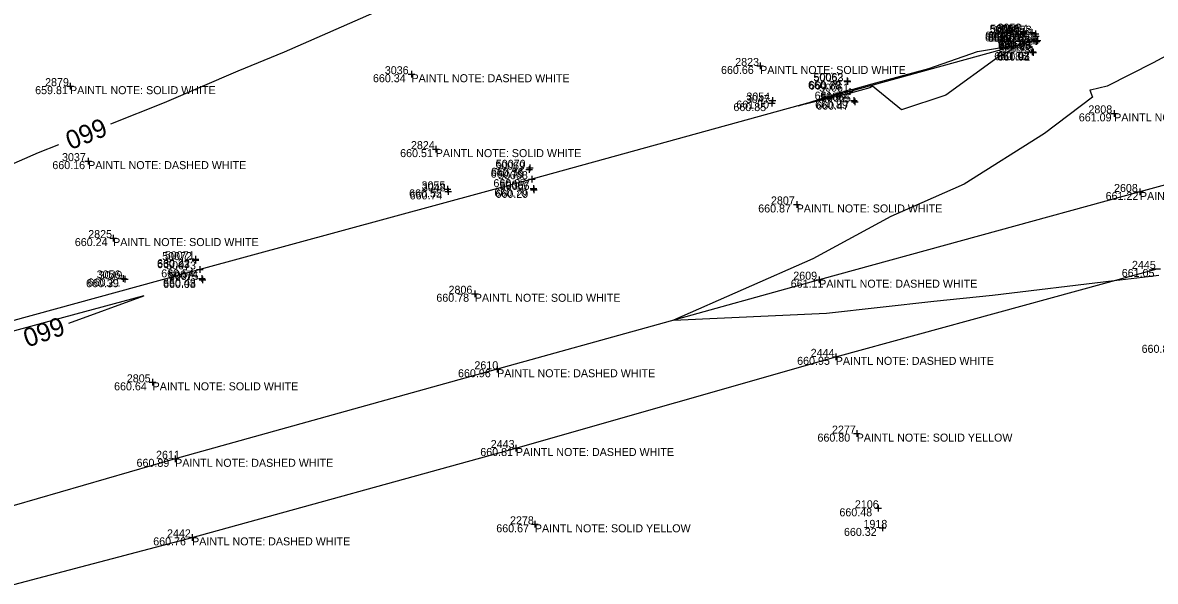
# Model space of a CAD drawing. Extents: x 2129350 to 2137777, y 657588 to 659885.
# Drawn here: x 2133578.5 to 2133748.4, y 658855.6 to 658939.3 of the extents above; entities that cross this region are included whole.
import ezdxf

# ---------------------------------------------------------------- set-up
doc = ezdxf.new("R2010")
doc.units = 0
for name, color, linetype in [('DT_X_Contour_Major', 7, 'Continuous'), ('DT_X_Contour_Minor', 7, 'Continuous'), ('PV_X_COP', 7, 'Continuous'), ('SV_X_Shot_Marker', 7, 'Continuous'), ('SV_X_Text_Comment', 7, 'Continuous'), ('SV_X_Text_Elevation', 7, 'Continuous'), ('SV_X_Text_Name', 7, 'Continuous')]:
    doc.layers.add(name, color=color, linetype=linetype)

msp = doc.modelspace()

# ---------------------------------------------------------------- linework, layer by layer
at = {"layer": 'DT_X_Contour_Major'}
for points in [[(2133591.75, 658924.14), (2133599.79, 658927.35), (2133610.86, 658932.13), (2133617.82, 658934.95), (2133634.09, 658942.09), (2133634.1, 658942.1), (2133634.22, 658942.15), (2133635.49, 658942.71), (2133639.66, 658944.47), (2133655.46, 658950.08), (2133660.34, 658951.83), (2133675.97, 658957.4), (2133684.82, 658960.59)], [(2133519.86, 658880.59), (2133520.81, 658880.85), (2133528.99, 658883.14), (2133535.75, 658885.05), (2133553.84, 658890.1), (2133553.85, 658890.1), (2133555.64, 658890.59), (2133556.82, 658890.91), (2133560.13, 658891.82), (2133558.94, 658891.52), (2133555.9, 658890.81), (2133550.49, 658894.1), (2133548.57, 658895.21), (2133555.23, 658903.95), (2133560.36, 658910.88), (2133564.1, 658912.51), (2133580.92, 658919.85), (2133583.95, 658921.04)], [(2133585.46, 658894.27), (2133596.7, 658898.35), (2133584.65, 658895.1), (2133581.35, 658894.2), (2133564.73, 658889.7), (2133557.21, 658887.65), (2133555.93, 658887.3), (2133555.26, 658887.12), (2133541.84, 658883.44), (2133531.15, 658880.51), (2133512.8, 658875.49), (2133511.75, 658875.21)]]:
    msp.add_lwpolyline(points, dxfattribs=at)
at = {"layer": 'DT_X_Contour_Minor'}
for points in [[(2133763.9, 658941.81), (2133748.12, 658933.31), (2133741.2, 658929.8), (2133738.68, 658929.2), (2133738.58, 658929.22), (2133738.99, 658928.18), (2133731.79, 658922.73), (2133719.77, 658915.11), (2133708.76, 658910.26), (2133697.07, 658903.92), (2133697.04, 658903.91), (2133676.14, 658894.71), (2133699.09, 658895.75), (2133715.18, 658897.58), (2133724.01, 658898.45), (2133742.27, 658900.65), (2133747.36, 658901.25), (2133748.96, 658901.49)], [(2133730.41, 658936.56), (2133730.2, 658936.88), (2133730.18, 658936.62), (2133730.41, 658936.56)], [(2133705.98, 658929.83), (2133705.62, 658929.56), (2133702.72, 658928.75), (2133699.84, 658928.05), (2133694.91, 658926.87), (2133700.9, 658928.74), (2133702.67, 658929.3), (2133703.09, 658929.35), (2133705.97, 658930.14), (2133714.45, 658932.47), (2133721.75, 658935.01), (2133728.35, 658936.11), (2133724.84, 658934.14), (2133716.98, 658928.46), (2133710.33, 658926.27), (2133705.98, 658929.83)]]:
    msp.add_lwpolyline(points, dxfattribs=at)
at = {"layer": 'PV_X_COP'}
for points in [[(2133730.22, 658936.63), (2133702.62, 658928.99), (2133654.91, 658915.86), (2133605.08, 658902.34), (2133554.92, 658888.56), (2133509.82, 658876.27), (2133459.08, 658862.07), (2133410.5, 658848.76), (2133362.33, 658835.49), (2133317.19, 658823.07), (2133266.35, 658808.95), (2133217.78, 658795.57), (2133170.89, 658782.95), (2133115.31, 658767.84), (2133063.51, 658753.59), (2133014.74, 658740.25), (2132963.88, 658726.32), (2132916.79, 658713.58), (2132868.39, 658700.1), (2132821.62, 658687.28), (2132770.55, 658673.15), (2132722.89, 658660.22), (2132675.02, 658647)], [(2133794.81, 658927.21), (2133746.12, 658913.94), (2133698.01, 658900.79), (2133649.69, 658887.36), (2133601.4, 658873.93), (2133553.07, 658859.93), (2133504.83, 658847.66), (2133456.81, 658834.24), (2133407.74, 658820.79), (2133360.25, 658807.48), (2133312.09, 658793.76), (2133264.31, 658781.06), (2133215.32, 658767.73), (2133166.74, 658754.23)], [(2133170.2, 658742.4), (2133218.35, 658756.09), (2133267.35, 658769.51), (2133315.65, 658782.23), (2133362.85, 658795.38), (2133411.68, 658809.49), (2133460, 658822.86), (2133507.59, 658836.18), (2133555.89, 658849.51), (2133603.94, 658862.15), (2133652.51, 658875.55), (2133700.49, 658889.22), (2133748.69, 658902.41)]]:
    msp.add_lwpolyline(points, dxfattribs=at)
at = {"layer": 'SV_X_Shot_Marker'}
for p, q in [((2133728.18, 658938.13), (2133728.18, 658937.13)), ((2133728.66, 658938.23), (2133728.66, 658937.23)), ((2133728.67, 658938.49), (2133728.67, 658937.49)), ((2133728.7, 658938.35), (2133728.7, 658937.35)), ((2133729.92, 658938.34), (2133729.92, 658937.34)), ((2133730.44, 658938.17), (2133730.44, 658937.17)), ((2133727.68, 658937.63), (2133728.68, 658937.63)), ((2133728.16, 658937.73), (2133729.16, 658937.73)), ((2133728.17, 658937.99), (2133729.17, 658937.99)), ((2133728.18, 658937.63), (2133728.18, 658937.63)), ((2133728.2, 658937.85), (2133729.2, 658937.85)), ((2133728.66, 658937.73), (2133728.66, 658937.73)), ((2133728.67, 658937.99), (2133728.67, 658937.99)), ((2133728.7, 658937.85), (2133728.7, 658937.85)), ((2133729.42, 658937.84), (2133730.42, 658937.84)), ((2133729.7, 658936.91), (2133730.7, 658936.91)), ((2133729.72, 658936.63), (2133730.72, 658936.63)), ((2133729.92, 658937.84), (2133729.92, 658937.84)), ((2133729.94, 658937.67), (2133730.94, 658937.67)), ((2133729.98, 658937.32), (2133730.98, 658937.32)), ((2133730, 658936.52), (2133731, 658936.52)), ((2133730.11, 658936.5), (2133731.11, 658936.5)), ((2133730.2, 658937.41), (2133730.2, 658936.41)), ((2133730.2, 658936.91), (2133730.2, 658936.91)), ((2133730.22, 658937.13), (2133730.22, 658936.13)), ((2133730.22, 658936.63), (2133730.22, 658936.63)), ((2133730.24, 658936.66), (2133731.24, 658936.66)), ((2133730.44, 658937.67), (2133730.44, 658937.67)), ((2133730.48, 658937.82), (2133730.48, 658936.82)), ((2133730.48, 658937.32), (2133730.48, 658937.32)), ((2133730.5, 658937.02), (2133730.5, 658936.02)), ((2133730.5, 658936.52), (2133730.5, 658936.52)), ((2133730.61, 658937), (2133730.61, 658936)), ((2133730.61, 658936.5), (2133730.61, 658936.5)), ((2133730.74, 658937.16), (2133730.74, 658936.16)), ((2133730.74, 658936.66), (2133730.74, 658936.66)), ((2133729.43, 658934.96), (2133730.43, 658934.96)), ((2133729.48, 658934.96), (2133730.48, 658934.96)), ((2133729.6, 658934.84), (2133730.6, 658934.84)), ((2133729.61, 658934.9), (2133730.61, 658934.9)), ((2133729.93, 658935.46), (2133729.93, 658934.46)), ((2133729.93, 658934.96), (2133729.93, 658934.96)), ((2133729.98, 658935.46), (2133729.98, 658934.46)), ((2133729.98, 658934.96), (2133729.98, 658934.96)), ((2133730.1, 658935.34), (2133730.1, 658934.34)), ((2133730.1, 658934.84), (2133730.1, 658934.84)), ((2133730.11, 658935.4), (2133730.11, 658934.4)), ((2133730.11, 658934.9), (2133730.11, 658934.9)), ((2133689.15, 658933.34), (2133689.15, 658932.34)), ((2133636.35, 658931.6), (2133637.35, 658931.6)), ((2133636.85, 658932.1), (2133636.85, 658931.1)), ((2133636.85, 658931.6), (2133636.85, 658931.6)), ((2133688.65, 658932.84), (2133689.65, 658932.84)), ((2133689.15, 658932.84), (2133689.15, 658932.84)), ((2133585.13, 658929.81), (2133586.13, 658929.81)), ((2133585.63, 658930.31), (2133585.63, 658929.31)), ((2133585.63, 658929.81), (2133585.63, 658929.81)), ((2133701.68, 658930.59), (2133702.68, 658930.59)), ((2133701.73, 658930.5), (2133702.73, 658930.5)), ((2133702.18, 658931.09), (2133702.18, 658930.09)), ((2133702.18, 658930.59), (2133702.18, 658930.59)), ((2133702.23, 658931), (2133702.23, 658930)), ((2133702.23, 658930.5), (2133702.23, 658930.5)), ((2133690.98, 658928.15), (2133690.98, 658927.15)), ((2133702.12, 658928.99), (2133703.12, 658928.99)), ((2133702.62, 658929.49), (2133702.62, 658928.49)), ((2133702.62, 658928.99), (2133702.62, 658928.99)), ((2133703.18, 658928.14), (2133703.18, 658927.14)), ((2133703.34, 658927.98), (2133703.34, 658926.98)), ((2133690.41, 658927.27), (2133691.41, 658927.27)), ((2133690.48, 658927.65), (2133691.48, 658927.65)), ((2133690.91, 658927.77), (2133690.91, 658926.77)), ((2133690.91, 658927.27), (2133690.91, 658927.27)), ((2133690.98, 658927.65), (2133690.98, 658927.65)), ((2133702.68, 658927.64), (2133703.68, 658927.64)), ((2133702.84, 658927.48), (2133703.84, 658927.48)), ((2133703.18, 658927.64), (2133703.18, 658927.64)), ((2133703.34, 658927.48), (2133703.34, 658927.48)), ((2133742.26, 658926.23), (2133742.26, 658925.23)), ((2133741.76, 658925.73), (2133742.76, 658925.73)), ((2133742.26, 658925.73), (2133742.26, 658925.73)), ((2133639.99, 658920.37), (2133640.99, 658920.37)), ((2133640.49, 658920.87), (2133640.49, 658919.87)), ((2133640.49, 658920.37), (2133640.49, 658920.37)), ((2133587.85, 658918.57), (2133588.85, 658918.57)), ((2133588.35, 658919.07), (2133588.35, 658918.07)), ((2133588.35, 658918.57), (2133588.35, 658918.57)), ((2133654.48, 658917.79), (2133654.48, 658916.79)), ((2133654.62, 658918.07), (2133654.62, 658917.07)), ((2133653.98, 658917.29), (2133654.98, 658917.29)), ((2133654.12, 658917.57), (2133655.12, 658917.57)), ((2133654.48, 658917.29), (2133654.48, 658917.29)), ((2133654.62, 658917.57), (2133654.62, 658917.57)), ((2133654.91, 658916.36), (2133654.91, 658915.36)), ((2133641.76, 658914.34), (2133642.76, 658914.34)), ((2133642.26, 658914.84), (2133642.26, 658913.84)), ((2133642.26, 658914.34), (2133642.26, 658914.34)), ((2133642.33, 658914.53), (2133642.33, 658913.53)), ((2133654.41, 658915.86), (2133655.41, 658915.86)), ((2133654.63, 658914.45), (2133655.63, 658914.45)), ((2133654.72, 658914.26), (2133655.72, 658914.26)), ((2133654.91, 658915.86), (2133654.91, 658915.86)), ((2133655.13, 658914.95), (2133655.13, 658913.95)), ((2133655.13, 658914.45), (2133655.13, 658914.45)), ((2133655.22, 658914.76), (2133655.22, 658913.76)), ((2133655.22, 658914.26), (2133655.22, 658914.26)), ((2133746.12, 658914.44), (2133746.12, 658913.44)), ((2133641.83, 658914.03), (2133642.83, 658914.03)), ((2133642.33, 658914.03), (2133642.33, 658914.03)), ((2133694.63, 658912.57), (2133694.63, 658911.57)), ((2133745.62, 658913.94), (2133746.62, 658913.94)), ((2133746.12, 658913.94), (2133746.12, 658913.94)), ((2133694.13, 658912.07), (2133695.13, 658912.07)), ((2133694.63, 658912.07), (2133694.63, 658912.07)), ((2133592.09, 658907.53), (2133592.09, 658906.53)), ((2133591.59, 658907.03), (2133592.59, 658907.03)), ((2133592.09, 658907.03), (2133592.09, 658907.03)), ((2133604.43, 658904.35), (2133604.43, 658903.35)), ((2133604.46, 658904.22), (2133604.46, 658903.22)), ((2133603.93, 658903.85), (2133604.93, 658903.85)), ((2133603.96, 658903.72), (2133604.96, 658903.72)), ((2133604.43, 658903.85), (2133604.43, 658903.85)), ((2133604.46, 658903.72), (2133604.46, 658903.72)), ((2133605.08, 658902.84), (2133605.08, 658901.84)), ((2133748.19, 658902.41), (2133749.19, 658902.41)), ((2133593.11, 658900.98), (2133594.11, 658900.98)), ((2133593.34, 658900.86), (2133594.34, 658900.86)), ((2133593.61, 658901.48), (2133593.61, 658900.48)), ((2133593.61, 658900.98), (2133593.61, 658900.98)), ((2133593.84, 658901.36), (2133593.84, 658900.36)), ((2133593.84, 658900.86), (2133593.84, 658900.86)), ((2133604.58, 658902.34), (2133605.58, 658902.34)), ((2133604.88, 658900.96), (2133605.88, 658900.96)), ((2133604.98, 658900.75), (2133605.98, 658900.75)), ((2133605.08, 658902.34), (2133605.08, 658902.34)), ((2133605.38, 658901.46), (2133605.38, 658900.46)), ((2133605.38, 658900.96), (2133605.38, 658900.96)), ((2133605.48, 658901.25), (2133605.48, 658900.25)), ((2133605.48, 658900.75), (2133605.48, 658900.75)), ((2133697.51, 658900.79), (2133698.51, 658900.79)), ((2133698.01, 658901.29), (2133698.01, 658900.29)), ((2133698.01, 658900.79), (2133698.01, 658900.79)), ((2133646.35, 658899.18), (2133646.35, 658898.18)), ((2133645.85, 658898.68), (2133646.85, 658898.68)), ((2133646.35, 658898.68), (2133646.35, 658898.68)), ((2133699.99, 658889.22), (2133700.99, 658889.22)), ((2133700.49, 658889.72), (2133700.49, 658888.72)), ((2133700.49, 658889.22), (2133700.49, 658889.22)), ((2133649.19, 658887.36), (2133650.19, 658887.36)), ((2133649.69, 658887.86), (2133649.69, 658886.86)), ((2133649.69, 658887.36), (2133649.69, 658887.36)), ((2133597.52, 658885.4), (2133598.52, 658885.4)), ((2133598.02, 658885.9), (2133598.02, 658884.9)), ((2133598.02, 658885.4), (2133598.02, 658885.4)), ((2133703.13, 658877.71), (2133704.13, 658877.71)), ((2133703.63, 658878.21), (2133703.63, 658877.21)), ((2133703.63, 658877.71), (2133703.63, 658877.71)), ((2133652.01, 658875.55), (2133653.01, 658875.55)), ((2133652.51, 658876.05), (2133652.51, 658875.05)), ((2133652.51, 658875.55), (2133652.51, 658875.55)), ((2133600.9, 658873.93), (2133601.9, 658873.93)), ((2133601.4, 658874.43), (2133601.4, 658873.43)), ((2133601.4, 658873.93), (2133601.4, 658873.93)), ((2133706.83, 658867.01), (2133706.83, 658866.01)), ((2133706.33, 658866.51), (2133707.33, 658866.51)), ((2133706.83, 658866.51), (2133706.83, 658866.51)), ((2133654.86, 658864.11), (2133655.86, 658864.11)), ((2133655.36, 658864.61), (2133655.36, 658863.61)), ((2133655.36, 658864.11), (2133655.36, 658864.11)), ((2133707.01, 658863.57), (2133708.01, 658863.57)), ((2133707.51, 658864.07), (2133707.51, 658863.07)), ((2133707.51, 658863.57), (2133707.51, 658863.57)), ((2133603.44, 658862.15), (2133604.44, 658862.15)), ((2133603.94, 658862.65), (2133603.94, 658861.65)), ((2133603.94, 658862.15), (2133603.94, 658862.15))]:
    msp.add_line(p, q, dxfattribs=at)

# ---------------------------------------------------------------- texts
at = {"layer": 'DT_X_Contour_Major'}
for rotation, p in [(201.661, (2133590.45, 658925.12)), (199.343, (2133584.2, 658895.31))]:
    msp.add_text('660', height=2.8, rotation=rotation, dxfattribs=at).set_placement(p)
at = {"layer": 'SV_X_Text_Comment'}
for s, p in [('PAINTL NOTE: DASHED WHITE', (2133636.85, 658930.4)), ('PAINTL NOTE: SOLID WHITE', (2133689.15, 658931.64)), ('PAINTL NOTE: SOLID WHITE', (2133585.63, 658928.61)), ('PAINTL NOTE: SOLID WHITE', (2133742.26, 658924.53)), ('PAINTL NOTE: SOLID WHITE', (2133640.49, 658919.17)), ('PAINTL NOTE: DASHED WHITE', (2133588.35, 658917.37)), ('PAINTL NOTE: DASHED WHITE', (2133746.12, 658912.74)), ('PAINTL NOTE: SOLID WHITE', (2133694.63, 658910.87)), ('PAINTL NOTE: SOLID WHITE', (2133592.09, 658905.83)), ('PAINTL NOTE: DASHED WHITE', (2133698.01, 658899.59)), ('PAINTL NOTE: SOLID WHITE', (2133646.35, 658897.48)), ('PAINTL NOTE: DASHED WHITE', (2133700.49, 658888.02)), ('PAINTL NOTE: DASHED WHITE', (2133649.69, 658886.16)), ('PAINTL NOTE: SOLID WHITE', (2133598.02, 658884.2)), ('PAINTL NOTE: SOLID YELLOW', (2133703.63, 658876.51)), ('PAINTL NOTE: DASHED WHITE', (2133652.51, 658874.35)), ('PAINTL NOTE: DASHED WHITE', (2133601.4, 658872.73)), ('PAINTL NOTE: SOLID YELLOW', (2133655.36, 658862.91)), ('PAINTL NOTE: DASHED WHITE', (2133603.94, 658860.95))]:
    msp.add_text(s, height=1.2, dxfattribs=at).set_placement(p)
at = {"layer": 'SV_X_Text_Elevation'}
for s, p in [('660.97', (2133722.87, 658936.53)), ('660.87', (2133722.9, 658936.79)), ('661.01', (2133723.31, 658936.43)), ('660.81', (2133723.36, 658936.65)), ('660.87', (2133724.15, 658936.65)), ('660.89', (2133724.66, 658936.47)), ('660.97', (2133724.69, 658936.12)), ('660.88', (2133724.83, 658935.3)), ('661.06', (2133724.85, 658935.43)), ('661.04', (2133724.91, 658935.71)), ('660.93', (2133724.95, 658935.46)), ('661.03', (2133725.2, 658935.32)), ('660.86', (2133724.26, 658933.7)), ('661.02', (2133724.64, 658933.76)), ('661.03', (2133724.68, 658933.76)), ('660.91', (2133724.74, 658933.64)), ('660.34', (2133631.07, 658930.4)), ('660.66', (2133683.28, 658931.64)), ('659.81', (2133580.4, 658928.61)), ('660.70', (2133696.33, 658929.4)), ('660.88', (2133696.45, 658929.3)), ('661.07', (2133697.32, 658927.79)), ('660.85', (2133685.14, 658926.07)), ('661.00', (2133685.57, 658926.45)), ('660.89', (2133697.4, 658926.44)), ('660.47', (2133697.56, 658926.29)), ('661.09', (2133736.95, 658924.53)), ('660.51', (2133635.15, 658919.17)), ('660.16', (2133582.98, 658917.37)), ('660.75', (2133648.72, 658916.09)), ('660.56', (2133648.77, 658916.37)), ('660.55', (2133636.49, 658913.14)), ('660.87', (2133649.14, 658914.66)), ('660.70', (2133649.28, 658913.25)), ('660.29', (2133649.45, 658913.06)), ('660.74', (2133636.58, 658912.83)), ('661.22', (2133740.97, 658912.74)), ('660.87', (2133688.86, 658910.87)), ('660.24', (2133586.35, 658905.83)), ('660.43', (2133598.68, 658902.52)), ('660.22', (2133598.69, 658902.66)), ('660.54', (2133599.31, 658901.14)), ('661.05', (2133743.39, 658901.2)), ('660.39', (2133588.04, 658899.66)), ('660.21', (2133588.29, 658899.78)), ('660.08', (2133599.59, 658899.55)), ('660.43', (2133599.59, 658899.76)), ('661.11', (2133693.73, 658899.59)), ('660.78', (2133640.58, 658897.48)), ('660.89', (2133746.37, 658889.82)), ('660.95', (2133694.7, 658888.02)), ('660.96', (2133643.83, 658886.16)), ('660.64', (2133592.24, 658884.2)), ('660.80', (2133697.75, 658876.51)), ('660.81', (2133647.17, 658874.35)), ('660.89', (2133595.61, 658872.73)), ('660.48', (2133701.04, 658865.31)), ('660.67', (2133649.57, 658862.91)), ('660.32', (2133701.72, 658862.37)), ('660.76', (2133598.11, 658860.95))]:
    msp.add_text(s, height=1.2, dxfattribs=at).set_placement(p)
at = {"layer": 'SV_X_Text_Name'}
for s, p in [('50056', (2133723.55, 658937.73)), ('50055', (2133723.66, 658937.85)), ('3046', (2133724.19, 658937.63)), ('3053', (2133724.77, 658937.99)), ('50054', (2133724.89, 658937.84)), ('50053', (2133725.41, 658937.67)), ('50057', (2133725.44, 658937.32)), ('3045', (2133726.29, 658936.91)), ('50060', (2133725.06, 658936.63)), ('50058', (2133725.45, 658936.52)), ('50052', (2133725.58, 658936.5)), ('3052', (2133726.85, 658936.66)), ('50059', (2133724.89, 658934.96)), ('50051', (2133725.51, 658934.9)), ('3044', (2133726.08, 658934.96)), ('3051', (2133726.63, 658934.84)), ('2823', (2133685.41, 658932.84)), ('3036', (2133632.85, 658931.6)), ('50062', (2133697.14, 658930.59)), ('50063', (2133697.18, 658930.5)), ('2879', (2133581.89, 658929.81)), ('50061', (2133698, 658928.99)), ('3047', (2133687, 658927.27)), ('3054', (2133687.08, 658927.65)), ('50064', (2133698.14, 658927.64)), ('50065', (2133698.28, 658927.48)), ('2808', (2133738.39, 658925.73)), ('2824', (2133636.77, 658920.37)), ('3037', (2133584.43, 658918.57)), ('50069', (2133649.41, 658917.29)), ('50070', (2133649.5, 658917.57)), ('50068', (2133649.84, 658915.86)), ('3055', (2133638.36, 658914.34)), ('3048', (2133638.41, 658914.03)), ('50067', (2133650.08, 658914.45)), ('50066', (2133650.09, 658914.26)), ('2608', (2133742.23, 658913.94)), ('2807', (2133690.77, 658912.07)), ('2825', (2133588.36, 658907.03)), ('50072', (2133599.45, 658903.72)), ('50071', (2133599.85, 658903.85)), ('50073', (2133600.06, 658902.34)), ('2445', (2133744.92, 658902.41)), ('3056', (2133589.63, 658900.98)), ('3049', (2133589.92, 658900.86)), ('50074', (2133600.37, 658900.96)), ('50075', (2133600.46, 658900.75)), ('2609', (2133694.12, 658900.79)), ('2806', (2133642.41, 658898.68)), ('2444', (2133696.73, 658889.22)), ('2610', (2133646.29, 658887.36)), ('2805', (2133594.15, 658885.4)), ('2277', (2133699.92, 658877.71)), ('2443', (2133648.74, 658875.55)), ('2611', (2133598.53, 658873.93)), ('2106', (2133703.36, 658866.51)), ('2278', (2133651.63, 658864.11)), ('2442', (2133600.18, 658862.15)), ('1918', (2133704.65, 658863.57))]:
    msp.add_text(s, height=1.2, dxfattribs=at).set_placement(p)

doc.saveas('drawing.dxf')
